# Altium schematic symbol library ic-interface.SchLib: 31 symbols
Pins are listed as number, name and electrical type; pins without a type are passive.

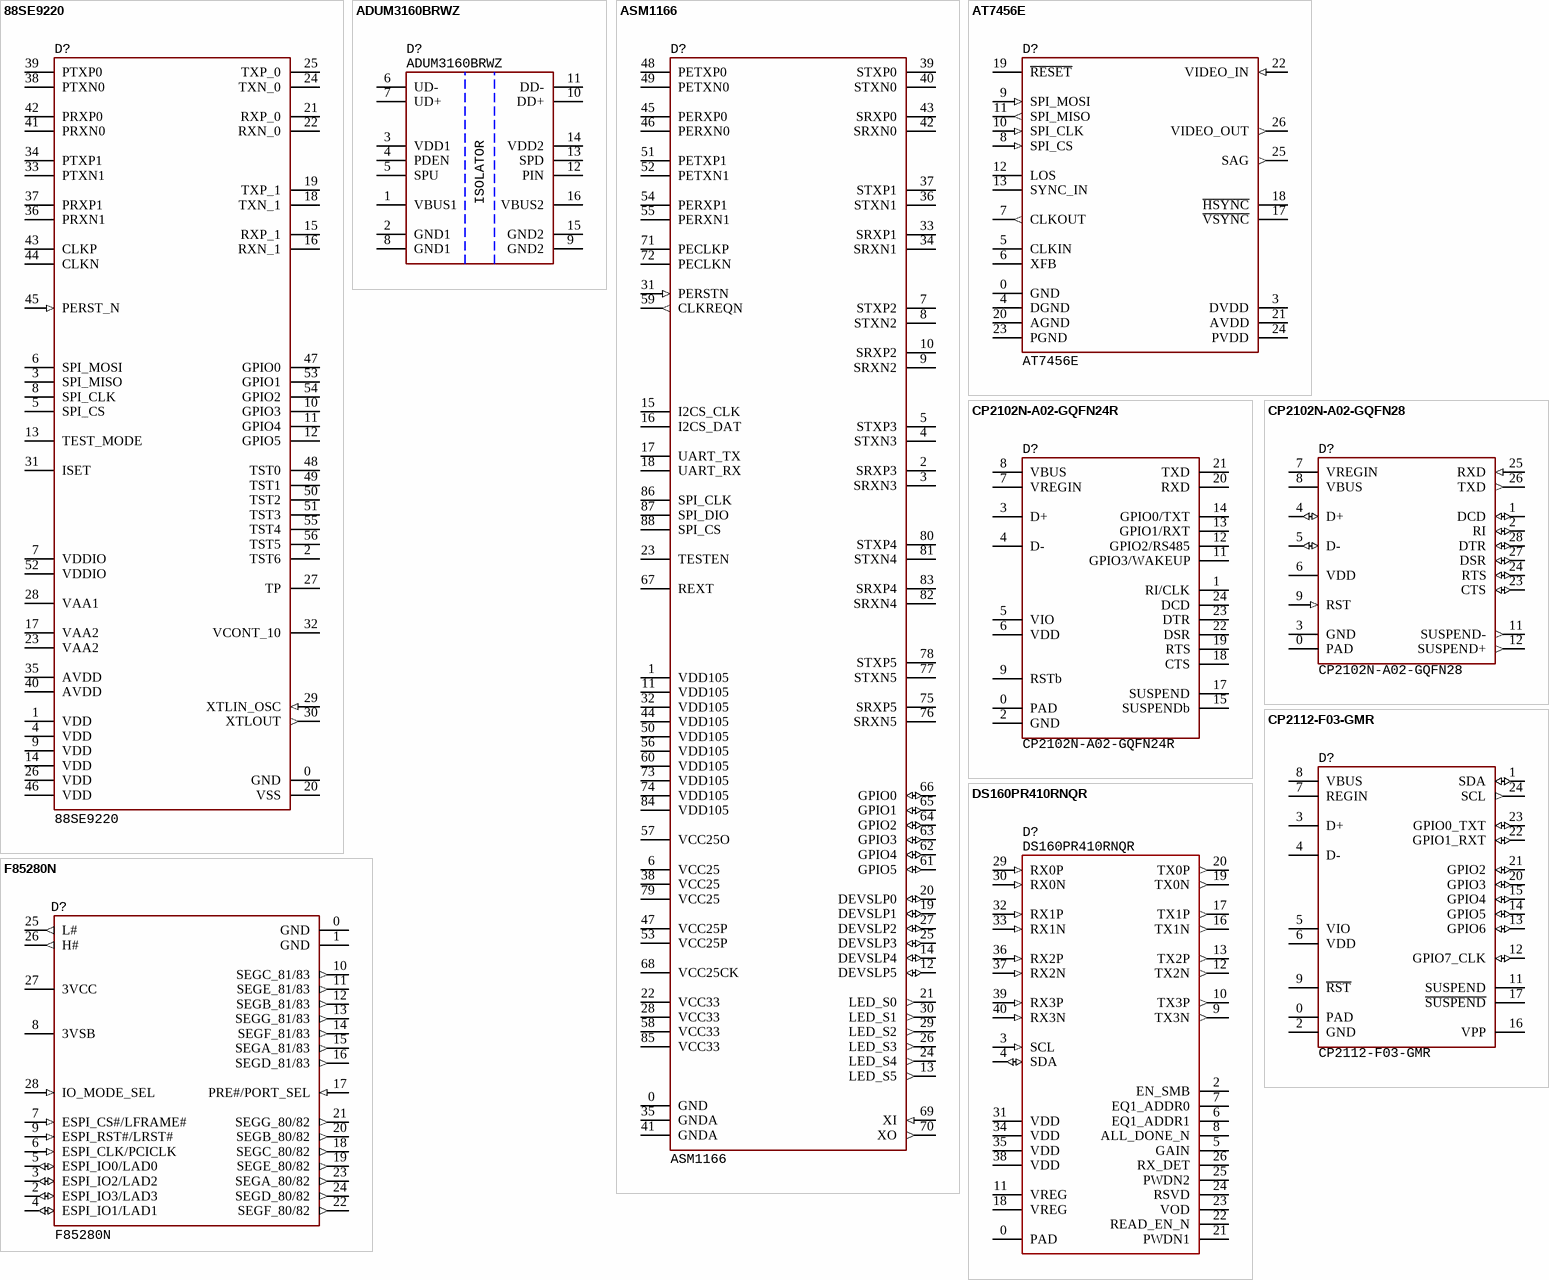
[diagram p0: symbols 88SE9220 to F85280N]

## 88SE9220
designator D?
PCIe Gen 2 to SATA, 2 HDDs, 6 GB/s, QFN-56, -40...+85°C; Manufacturer: Marvell
footprint 56-QFN (7x7, pitch 0.4) (7x7 mm, pitch 0.4 mm, power pad)
pins: 0 GND, 1 VDD, 2 TST6, 3 SPI_MISO, 4 VDD, 5 SPI_CS, 6 SPI_MOSI, 7 VDDIO, 8 SPI_CLK, 9 VDD, 10 GPIO3, 11 GPIO4, 12 GPIO5, 13 TEST_MODE, 14 VDD, 15 RXP_1, 16 RXN_1, 17 VAA2, 18 TXN_1, 19 TXP_1, 20 VSS, 21 RXP_0, 22 RXN_0, 23 VAA2, 24 TXN_0, 25 TXP_0, 26 VDD, 27 TP, 28 VAA1, 29 XTLIN_OSC (in), 30 XTLOUT (out), 31 ISET, 32 VCONT_10, 33 PTXN1, 34 PTXP1, 35 AVDD, 36 PRXN1, 37 PRXP1, 38 PTXN0, 39 PTXP0, 40 AVDD, 41 PRXN0, 42 PRXP0, 43 CLKP, 44 CLKN, 45 PERST_N (in), 46 VDD, 47 GPIO0, 48 TST0, 49 TST1, 50 TST2, 51 TST3, 52 VDDIO, 53 GPIO1, 54 GPIO2, 55 TST4, 56 TST5

## ADUM3160BRWZ
designator D?
USB isolator, 12 Mb/s, supply 3.1...5.5V, 2500 Vrms, SOIC-16, -40...+85°C; Manufacture: Analog Devices
footprint 16-TSSOP (pitch 1.27 mm)
pins: 1 VBUS1, 2 GND1, 3 VDD1, 4 PDEN, 5 SPU, 6 UD-, 7 UD+, 8 GND1, 9 GND2, 10 DD+, 11 DD-, 12 PIN, 13 SPD, 14 VDD2, 15 GND2, 16 VBUS2

## ASM1166
designator D?
PCIe Gen 2 to SATA, 6 HDDs, 6 GB/s, QFN-88, -40...+85°C; Manufacturer: ASMedia
footprint 88-QFN (10x10, pitch 0.4) (10x10 mm, pitch 0.4 mm, power pad)
pins: 0 GND, 1 VDD105, 2 SRXP3, 3 SRXN3, 4 STXN3, 5 STXP3, 6 VCC25, 7 STXP2, 8 STXN2, 9 SRXN2, 10 SRXP2, 11 VDD105, 12 DEVSLP5 (io), 13 LED_S5 (out), 14 DEVSLP4 (io), 15 I2CS_CLK, 16 I2CS_DAT, 17 UART_TX, 18 UART_RX, 19 DEVSLP1 (io), 20 DEVSLP0 (io), 21 LED_S0 (out), 22 VCC33, 23 TESTEN, 24 LED_S4 (out), 25 DEVSLP3 (io), 26 LED_S3 (out), 27 DEVSLP2 (io), 28 VCC33, 29 LED_S2 (out), 30 LED_S1 (out), 31 PERSTN (in), 32 VDD105, 33 SRXP1, 34 SRXN1, 35 GNDA, 36 STXN1, 37 STXP1, 38 VCC25, 39 STXP0, 40 STXN0, 41 GNDA, 42 SRXN0, 43 SRXP0, 44 VDD105, 45 PERXP0, 46 PERXN0, 47 VCC25P, 48 PETXP0, 49 PETXN0, 50 VDD105, 51 PETXP1, 52 PETXN1, 53 VCC25P, 54 PERXP1, 55 PERXN1, 56 VDD105, 57 VCC25O, 58 VCC33, 59 CLKREQN (out), 60 VDD105, 61 GPIO5 (io), 62 GPIO4 (io), 63 GPIO3 (io), 64 GPIO2 (io), 65 GPIO1 (io), 66 GPIO0 (io), 67 REXT, 68 VCC25CK, 69 XI (in), 70 XO (out), 71 PECLKP, 72 PECLKN, 73 VDD105, 74 VDD105, 75 SRXP5, 76 SRXN5, 77 STXN5, 78 STXP5, 79 VCC25, 80 STXP4, 81 STXN4, 82 SRXN4, 83 SRXP4, 84 VDD105, 85 VCC33, 86 SPI_CLK, 87 SPI_DIO, 88 SPI_CS

## AT7456E
designator D?
OSD generator, supply 3.15...5.25V, TSSOP-28, -40...+85°C; Manufacturer: ZHONGKEWEI
footprint 28-TSSOP-PAD (pitch 0.65 mm)
pins: 0 GND, 3 DVDD, 4 DGND, 5 CLKIN, 6 XFB, 7 CLKOUT (out), 8 SPI_CS (in), 9 SPI_MOSI (in), 10 SPI_CLK (in), 11 SPI_MISO (out), 12 LOS, 13 SYNC_IN, 17 ~{VSYNC}, 18 ~{HSYNC}, 19 ~{RESET}, 20 AGND, 21 AVDD, 22 VIDEO_IN (in), 23 PGND, 24 PVDD, 25 SAG (out), 26 VIDEO_OUT (out)

## CP2102N-A02-GQFN24R
designator D?
USB-to-UART, USB2.0, QFN-24, 3...3.6V, -40...+85°C; Manufacturer: Silicon Labs
footprint 24-QFN (4x4, pitch 0.5) (4x4 mm, pitch 0.5 mm, power pad)
pins: 0 PAD, 1 RI/CLK, 2 GND, 3 D+, 4 D-, 5 VIO, 6 VDD, 7 VREGIN, 8 VBUS, 9 RSTb, 11 GPIO3/WAKEUP, 12 GPIO2/RS485, 13 GPIO1/RXT, 14 GPIO0/TXT, 15 SUSPENDb, 17 SUSPEND, 18 CTS, 19 RTS, 20 RXD, 21 TXD, 22 DSR, 23 DTR, 24 DCD

## CP2102N-A02-GQFN28
designator D?  PartNumber: CP2102N-A02-GQFN28
USB-to-UART, USB2.0, QFN-28, 3...3.6V, -40...+85°C; Manufacturer: Silicon Labs
footprint 28-QFN (5x5, pitch 0.5) (5x5 mm, pitch 0.5 mm, power pad)
pins: 0 PAD, 1 DCD (io), 2 RI (io), 3 GND, 4 D+ (io), 5 D- (io), 6 VDD, 7 VREGIN, 8 VBUS, 9 RST (in), 11 SUSPEND- (out), 12 SUSPEND+ (out), 23 CTS (io), 24 RTS (io), 25 RXD (in), 26 TXD (out), 27 DSR (io), 28 DTR (io)

## CP2112-F03-GMR
designator D?
USB-to-I2C, USB2.0, QFN-24, 3...3.6V, -40...+85°C; Manufacturer: Silicon Labs
footprint 24-QFN (4x4, pitch 0.5) (4x4 mm, pitch 0.5 mm, power pad)
pins: 0 PAD, 1 SDA (io), 2 GND, 3 D+, 4 D-, 5 VIO, 6 VDD, 7 REGIN, 8 VBUS, 9 ~{RST}, 11 SUSPEND, 12 GPIO7_CLK (io), 13 GPIO6 (io), 14 GPIO5 (io), 15 GPIO4 (io), 16 VPP, 17 ~{SUSPEND}, 20 GPIO3 (io), 21 GPIO2 (io), 22 GPIO1_RXT (io), 23 GPIO0_TXT (io), 24 SCL (out)

## DS160PR410RNQR
designator D?
Redriver, PCIe Gen 4, 25 GT/s, supply 3...3.6V, 150 mA, -40...+85°C; Manufacture: Texas Instruments
footprint 40-WQFN (6x4, pitch 0.4) (PQFN, 40-Leads, Body 6,00x4,00mm, Pitch 0,40mm, Thermal Pad 4,70x2,70mm, IPC Medium Density)
pins: 0 PAD, 2 EN_SMB, 3 SCL (in), 4 SDA (io), 5 GAIN, 6 EQ1_ADDR1, 7 EQ1_ADDR0, 8 ALL_DONE_N, 9 TX3N (out), 10 TX3P (out), 11 VREG, 12 TX2N (out), 13 TX2P (out), 16 TX1N (out), 17 TX1P (out), 18 VREG, 19 TX0N (out), 20 TX0P (out), 21 PWDN1, 22 READ_EN_N, 23 VOD, 24 RSVD, 25 PWDN2, 26 RX_DET, 29 RX0P (in), 30 RX0N (in), 31 VDD, 32 RX1P (in), 33 RX1N (in), 34 VDD, 35 VDD, 36 RX2P (in), 37 RX2N (in), 38 VDD, 39 RX3P (in), 40 RX3N (in)

## F85280N
designator D?
LPC eSPI interface, 3.3V, QFN-28, -40...+85°C; Manufacturer: Fintek
footprint 28-QFN (4x4, pitch 0.45) (4x4 mm, pitch 0.45 mm, power pad)
pins: 0 GND (power), 1 GND (power), 2 ESPI_IO3/LAD3 (io), 3 ESPI_IO2/LAD2 (io), 4 ESPI_IO1/LAD1 (io), 5 ESPI_IO0/LAD0 (io), 6 ESPI_CLK/PCICLK (in), 7 ESPI_CS#/LFRAME# (in), 8 3VSB (power), 9 ESPI_RST#/LRST# (in), 10 SEGC_81/83 (out), 11 SEGE_81/83 (out), 12 SEGB_81/83 (out), 13 SEGG_81/83 (out), 14 SEGF_81/83 (out), 15 SEGA_81/83 (out), 16 SEGD_81/83 (out), 17 PRE#/PORT_SEL (in), 18 SEGC_80/82 (out), 19 SEGE_80/82 (out), 20 SEGB_80/82 (out), 21 SEGG_80/82 (out), 22 SEGF_80/82 (out), 23 SEGA_80/82 (out), 24 SEGD_80/82 (out), 25 L# (out), 26 H# (out), 27 3VCC (power), 28 IO_MODE_SEL (in)

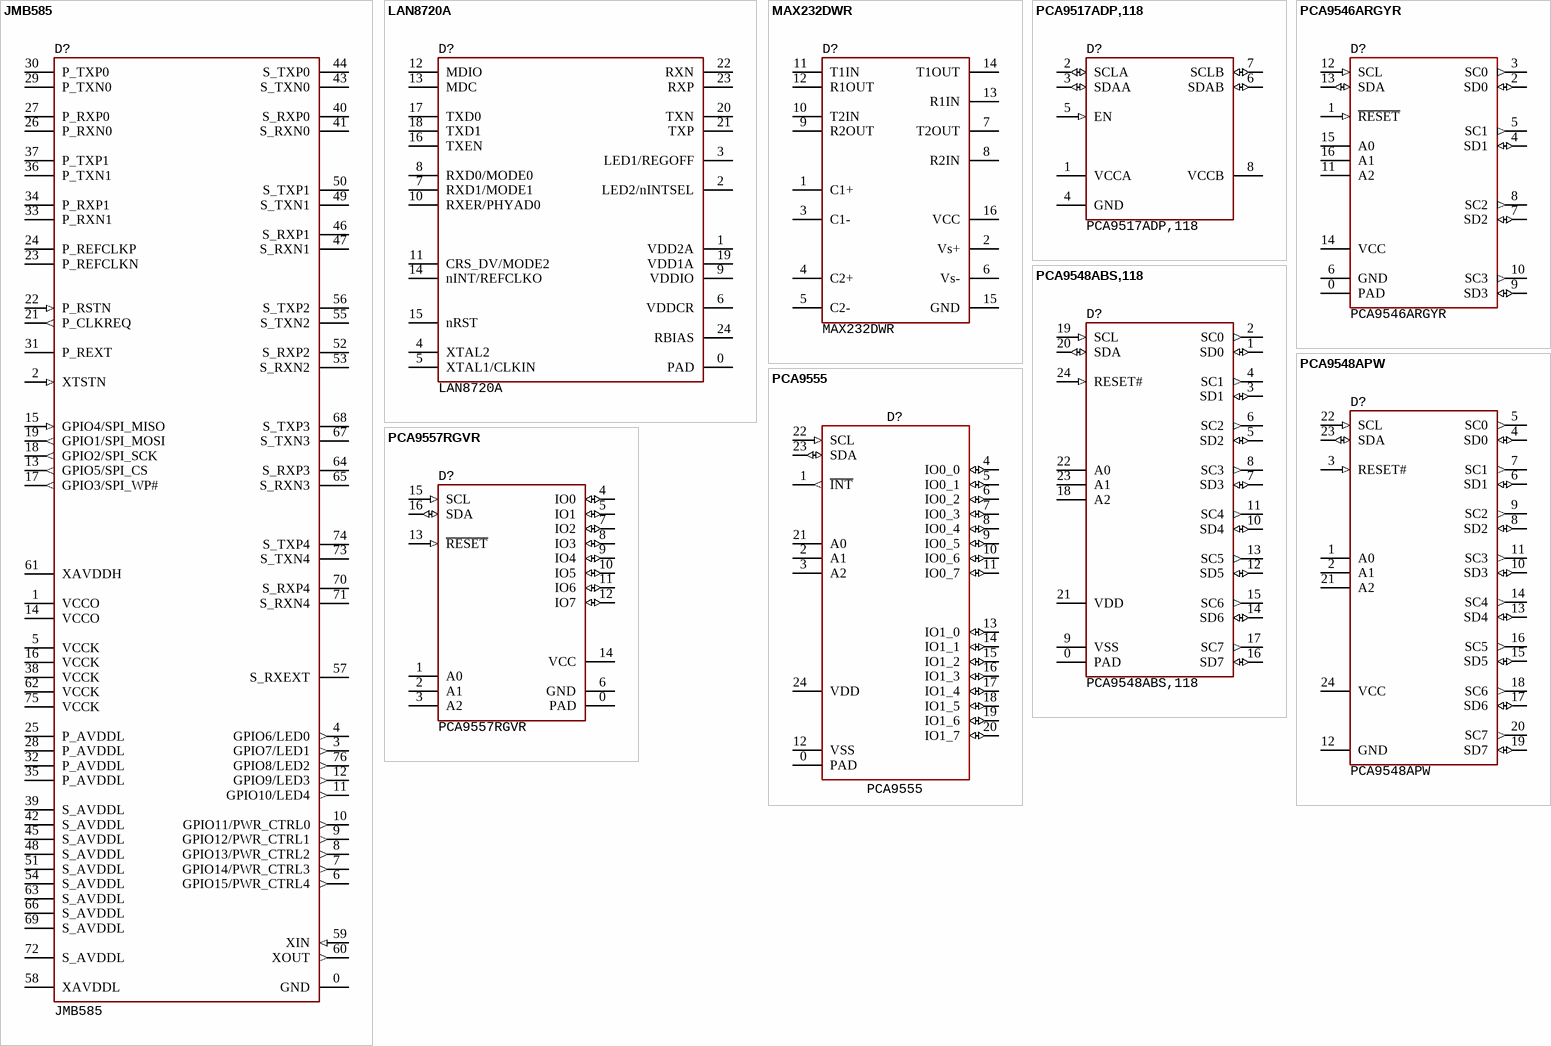
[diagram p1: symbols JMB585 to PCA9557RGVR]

## JMB585
designator D?
PCIe Gen 3 to SATA, 5 HDDs, 6 GB/s, QFN-76, -40...+85°C; Manufacturer: JMicron
footprint 76-QFN (9x9, pitch 0.4) (9x9 mm, pitch 0.4 mm, power pad)
pins: 0 GND, 1 VCCO, 2 XTSTN (in), 3 GPIO7/LED1 (out), 4 GPIO6/LED0 (out), 5 VCCK, 6 GPIO15/PWR_CTRL4 (out), 7 GPIO14/PWR_CTRL3 (out), 8 GPIO13/PWR_CTRL2 (out), 9 GPIO12/PWR_CTRL1 (out), 10 GPIO11/PWR_CTRL0 (out), 11 GPIO10/LED4 (out), 12 GPIO9/LED3 (out), 13 GPIO5/SPI_CS (out), 14 VCCO, 15 GPIO4/SPI_MISO (in), 16 VCCK, 17 GPIO3/SPI_WP# (out), 18 GPIO2/SPI_SCK (out), 19 GPIO1/SPI_MOSI (out), 21 P_CLKREQ (out), 22 P_RSTN (in), 23 P_REFCLKN, 24 P_REFCLKP, 25 P_AVDDL, 26 P_RXN0, 27 P_RXP0, 28 P_AVDDL, 29 P_TXN0, 30 P_TXP0, 31 P_REXT, 32 P_AVDDL, 33 P_RXN1, 34 P_RXP1, 35 P_AVDDL, 36 P_TXN1, 37 P_TXP1, 38 VCCK, 39 S_AVDDL, 40 S_RXP0, 41 S_RXN0, 42 S_AVDDL, 43 S_TXN0, 44 S_TXP0, 45 S_AVDDL, 46 S_RXP1, 47 S_RXN1, 48 S_AVDDL, 49 S_TXN1, 50 S_TXP1, 51 S_AVDDL, 52 S_RXP2, 53 S_RXN2, 54 S_AVDDL, 55 S_TXN2, 56 S_TXP2, 57 S_RXEXT, 58 XAVDDL, 59 XIN (in), 60 XOUT (out), 61 XAVDDH, 62 VCCK, 63 S_AVDDL, 64 S_RXP3, 65 S_RXN3, 66 S_AVDDL, 67 S_TXN3, 68 S_TXP3, 69 S_AVDDL, 70 S_RXP4, 71 S_RXN4, 72 S_AVDDL, 73 S_TXN4, 74 S_TXP4, 75 VCCK, 76 GPIO8/LED2 (out)

## LAN8720A
designator D?  PartNumber: LAN8720A
Ethernet PHY, 10/100 Mbps, RMII, supply 1.6...3.6V, QFN-24, 0...+85°C; Manufacturer: Microchip Technology
footprint 24-QFN (4x4, pitch 0.5) (4x4 mm, pitch 0.5 mm, power pad)
pins: 0 PAD, 1 VDD2A, 2 LED2/nINTSEL, 3 LED1/REGOFF, 4 XTAL2, 5 XTAL1/CLKIN, 6 VDDCR, 7 RXD1/MODE1, 8 RXD0/MODE0, 9 VDDIO, 10 RXER/PHYAD0, 11 CRS_DV/MODE2, 12 MDIO, 13 MDC, 14 nINT/REFCLKO, 15 nRST, 16 TXEN, 17 TXD0, 18 TXD1, 19 VDD1A, 20 TXN, 21 TXP, 22 RXN, 23 RXP, 24 RBIAS

## MAX232DWR
designator D?
RS232-to-UART, USB2.0, TSSOP-16, supply 4.5...5.5V, -65...+150°C; Manufacturer: Texas Instruments
footprint 16-TSSOP (pitch 1.27 mm)
pins: 1 C1+, 2 Vs+, 3 C1-, 4 C2+, 5 C2-, 6 Vs-, 7 T2OUT, 8 R2IN, 9 R2OUT, 10 T2IN, 11 T1IN, 12 R1OUT, 13 R1IN, 14 T1OUT, 15 GND, 16 VCC

## PCA9517ADP,118
designator D?
I2C/SMBus repeater and level shifter, 2.7...5.5V, TSSOP-8, -40...+85°C; Manufacturer: NXP; Manufacturer: NXP Semiconductors
footprint 8-MSOP (pitch 0.65 mm)
pins: 1 VCCA, 2 SCLA (io), 3 SDAA (io), 4 GND, 5 EN (in), 6 SDAB (io), 7 SCLB (io), 8 VCCB

## PCA9546ARGYR
designator D?
I2C/SMBus switch, 4 channels, 2.3...5.5V, VQFN-16, -40...+85°C; Manufacturer: Texas Instruments
footprint 16-QFN (4x4) (4x4 mm, pitch 0.65 mm)
pins: 0 PAD, 1 ~{RESET} (in), 2 SD0 (io), 3 SC0 (out), 4 SD1 (io), 5 SC1 (out), 6 GND, 7 SD2 (io), 8 SC2 (out), 9 SD3 (io), 10 SC3 (out), 11 A2, 12 SCL (in), 13 SDA (io), 14 VCC, 15 A0, 16 A1

## PCA9548ABS,118
designator D?
I2C/SMBus switch, 8 channels, 2.3...5.5V, QFN-24, -40...+85°C; Manufacturer: NXP
footprint 24-QFN (4x4, pitch 0.5) (4x4 mm, pitch 0.5 mm, power pad)
pins: 0 PAD, 1 SD0 (io), 2 SC0 (out), 3 SD1 (io), 4 SC1 (out), 5 SD2 (io), 6 SC2 (out), 7 SD3 (io), 8 SC3 (out), 9 VSS, 10 SD4 (io), 11 SC4 (out), 12 SD5 (io), 13 SC5 (out), 14 SD6 (io), 15 SC6 (out), 16 SD7 (io), 17 SC7 (out), 18 A2, 19 SCL (in), 20 SDA (io), 21 VDD, 22 A0, 23 A1, 24 RESET# (in)

## PCA9548APW
designator D?
I2C/SMBus switch, 8 channels, 2.3...5.5V, TSSOP-24, -40...+85°C; Manufacturer: Texas instruments
footprint 24-TSSOP (4x4 mm, pitch 0.5 mm, power pad)
pins: 1 A0, 2 A1, 3 RESET# (in), 4 SD0 (io), 5 SC0 (out), 6 SD1 (io), 7 SC1 (out), 8 SD2 (io), 9 SC2 (out), 10 SD3 (io), 11 SC3 (out), 12 GND, 13 SD4 (io), 14 SC4 (out), 15 SD5 (io), 16 SC5 (out), 17 SD6 (io), 18 SC6 (out), 19 SD7 (io), 20 SC7 (out), 21 A2, 22 SCL (in), 23 SDA (io), 24 VCC

## PCA9555
designator D?
I2C/SMBus I/O port with interrupt, 2.3...5.5V, VQFN-24, -40...+85°C; Manufacturer: Texas instruments; Manufacturer Part Number: TCA9548ARGER
footprint 24-QFN (4x4, pitch 0.5) (4x4 mm, pitch 0.5 mm, power pad)
pins: 0 PAD, 1 ~{INT} (out), 2 A1, 3 A2, 4 IO0_0 (io), 5 IO0_1 (io), 6 IO0_2 (io), 7 IO0_3 (io), 8 IO0_4 (io), 9 IO0_5 (io), 10 IO0_6 (io), 11 IO0_7 (io), 12 VSS, 13 IO1_0 (io), 14 IO1_1 (io), 15 IO1_2 (io), 16 IO1_3 (io), 17 IO1_4 (io), 18 IO1_5 (io), 19 IO1_6 (io), 20 IO1_7 (io), 21 A0, 22 SCL (in), 23 SDA (io), 24 VDD

## PCA9557RGVR
designator D?
I2C/SMBus IO Extender, 8 channels, 1.65...5.5V, QFN-16, -40...+85°C; Manufacturer: Texas Instruments
footprint 16-QFN (4x4) (4x4 mm, pitch 0.65 mm)
pins: 0 PAD, 1 A0, 2 A1, 3 A2, 4 IO0 (io), 5 IO1 (io), 6 GND, 7 IO2 (io), 8 IO3 (io), 9 IO4 (io), 10 IO5 (io), 11 IO6 (io), 12 IO7 (io), 13 ~{RESET} (in), 14 VCC, 15 SCL (in), 16 SDA (io)

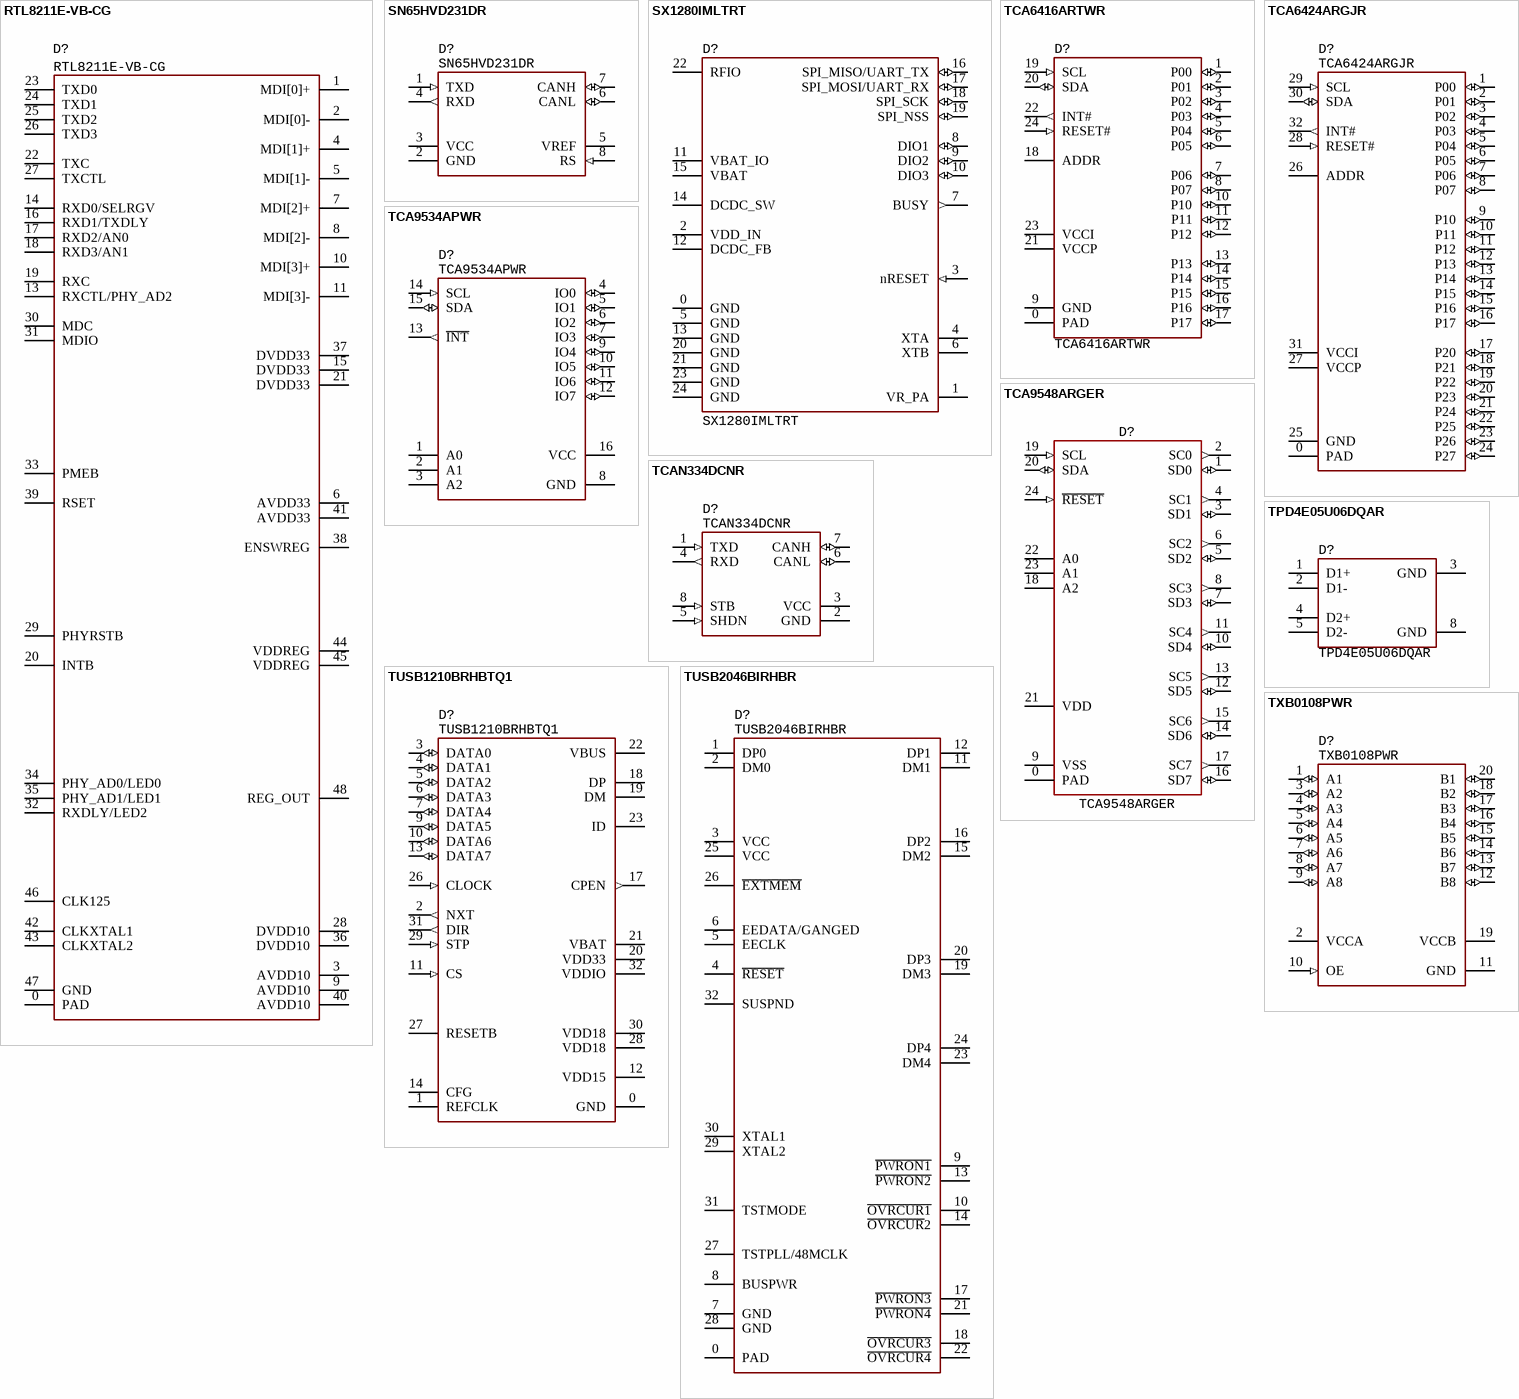
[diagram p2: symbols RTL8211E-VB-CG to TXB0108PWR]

## RTL8211E-VB-CG
designator D?
Ethernet PHY, 10/100/1000 Mbps, RGMII, supply 1.05/3.3V, QFN-48, 0...+70°C; Manufacturer: Realtek
footprint 48-QFN (6x6, pitch 0.4) (6x6 mm, pitch 0.4 mm, power pad)
pins: 0 PAD, 1 MDI[0]+, 2 MDI[0]-, 3 AVDD10, 4 MDI[1]+, 5 MDI[1]-, 6 AVDD33, 7 MDI[2]+, 8 MDI[2]-, 9 AVDD10, 10 MDI[3]+, 11 MDI[3]-, 13 RXCTL/PHY_AD2, 14 RXD0/SELRGV, 15 DVDD33, 16 RXD1/TXDLY, 17 RXD2/AN0, 18 RXD3/AN1, 19 RXC, 20 INTB, 21 DVDD33, 22 TXC, 23 TXD0, 24 TXD1, 25 TXD2, 26 TXD3, 27 TXCTL, 28 DVDD10, 29 PHYRSTB, 30 MDC, 31 MDIO, 32 RXDLY/LED2, 33 PMEB, 34 PHY_AD0/LED0, 35 PHY_AD1/LED1, 36 DVDD10, 37 DVDD33, 38 ENSWREG, 39 RSET, 40 AVDD10, 41 AVDD33, 42 CLKXTAL1, 43 CLKXTAL2, 44 VDDREG, 45 VDDREG, 46 CLK125, 47 GND, 48 REG_OUT

## SN65HVD231DR
designator D?
CAN, 1 Mb/s, supply 3...3.6V, SOIC-8, -40...+85°C; Manufacturer: Texas Instruments
footprint 8-SOIC (pitch 1.27 mm)
pins: 1 TXD (in), 2 GND, 3 VCC, 4 RXD (out), 5 VREF, 6 CANL (io), 7 CANH (io), 8 RS (in)

## SX1280IMLTRT
designator D?
LoRa, 2.4 GHz, 1.3 Mb/s, 12.5 dBm, supply 1.8...3.7V, QFN-24, -40...+85°C; Manufacturer: Semtech
footprint 24-QFN (4x4, pitch 0.5) (4x4 mm, pitch 0.5 mm, power pad)
pins: 0 GND, 1 VR_PA, 2 VDD_IN, 3 nRESET (in), 4 XTA, 5 GND, 6 XTB, 7 BUSY (out), 8 DIO1 (io), 9 DIO2 (io), 10 DIO3 (io), 11 VBAT_IO, 12 DCDC_FB, 13 GND, 14 DCDC_SW, 15 VBAT, 16 SPI_MISO/UART_TX (io), 17 SPI_MOSI/UART_RX (io), 18 SPI_SCK (io), 19 SPI_NSS (io), 20 GND, 21 GND, 22 RFIO, 23 GND, 24 GND

## TCA6416ARTWR
designator D?
I2C/SMBus IO Expander, 16 I/O, 1.65...5.5V, WQFN-24, -40...+85°C; Manufacturer: Texas instruments
footprint 24-QFN (4x4, pitch 0.5) (4x4 mm, pitch 0.5 mm, power pad)
pins: 0 PAD, 1 P00 (io), 2 P01 (io), 3 P02 (io), 4 P03 (io), 5 P04 (io), 6 P05 (io), 7 P06 (io), 8 P07 (io), 9 GND, 10 P10 (io), 11 P11 (io), 12 P12 (io), 13 P13 (io), 14 P14 (io), 15 P15 (io), 16 P16 (io), 17 P17 (io), 18 ADDR, 19 SCL (in), 20 SDA (io), 21 VCCP, 22 INT# (out), 23 VCCI, 24 RESET# (in)

## TCA6424ARGJR
designator D?
I2C/SMBus IO Extender, 24 channels, 25 mA, 1.65...5.5V, QFN-32, -40...+85°C; Manufacturer: Texas Instruments
footprint 32-QFN (5x5, pitch 0.5) (5x5 mm, pitch 0.5 mm, power pad)
pins: 0 PAD, 1 P00 (io), 2 P01 (io), 3 P02 (io), 4 P03 (io), 5 P04 (io), 6 P05 (io), 7 P06 (io), 8 P07 (io), 9 P10 (io), 10 P11 (io), 11 P12 (io), 12 P13 (io), 13 P14 (io), 14 P15 (io), 15 P16 (io), 16 P17 (io), 17 P20 (io), 18 P21 (io), 19 P22 (io), 20 P23 (io), 21 P24 (io), 22 P25 (io), 23 P26 (io), 24 P27 (io), 25 GND, 26 ADDR, 27 VCCP, 28 RESET# (in), 29 SCL (in), 30 SDA (io), 31 VCCI, 32 INT# (out)

## TCA9534APWR
designator D?
I2C/SMBus IO Extender, 8 channels, 25 mA, 1.65...5.5V, TSSOP-16, -40...+85°C; Manufacturer: Texas Instruments
footprint 16-SSOP (pitch 0.635 mm)
pins: 1 A0, 2 A1, 3 A2, 4 IO0 (io), 5 IO1 (io), 6 IO2 (io), 7 IO3 (io), 8 GND, 9 IO4 (io), 10 IO5 (io), 11 IO6 (io), 12 IO7 (io), 13 ~{INT} (out), 14 SCL (in), 15 SDA (io), 16 VCC

## TCA9548ARGER
designator D?
I2C/SMBus switch, 8 channels, 1.65...5.5V, VQFN-24, -40...+85°C; Manufacturer: Texas instruments
footprint 24-QFN (4x4, pitch 0.5) (4x4 mm, pitch 0.5 mm, power pad)
pins: 0 PAD, 1 SD0 (io), 2 SC0 (out), 3 SD1 (io), 4 SC1 (out), 5 SD2 (io), 6 SC2 (out), 7 SD3 (io), 8 SC3 (out), 9 VSS, 10 SD4 (io), 11 SC4 (out), 12 SD5 (io), 13 SC5 (out), 14 SD6 (io), 15 SC6 (out), 16 SD7 (io), 17 SC7 (out), 18 A2, 19 SCL (in), 20 SDA (io), 21 VDD, 22 A0, 23 A1, 24 ~{RESET} (in)

## TCAN334DCNR
designator D?
CAN, 1 Mb/s, supply 3...3.6V, SOT23-8, -40...+85°C; Manufacturer: Texas Instruments
footprint SOT23-8 (pitch 0.95 mm)
pins: 1 TXD (in), 2 GND, 3 VCC, 4 RXD (out), 5 SHDN (in), 6 CANL (io), 7 CANH (io), 8 STB (in)

## TPD4E05U06DQAR
designator D?
Protection ESD, 5.5V, 4 channels, 0.5 pF, 5A peak, uDFN-10, -40...+125°C; Manufacturer: Texas Instruments
footprint 10-DFN (2.5x1) (3x3 mm, pitch 0.5 mm, power pad)
pins: 1 D1+, 2 D1-, 3 GND, 4 D2+, 5 D2-, 8 GND

## TUSB1210BRHBTQ1
designator D?
USB2.0 PHY, 480 Mb/s, supply 2.7...4.8V, QFN-32, -40...+85°C; Manufacturer: Texas Instruments
footprint 32-QFN (5x5, pitch 0.5) (5x5 mm, pitch 0.5 mm, power pad)
pins: 0 GND, 1 REFCLK, 2 NXT (out), 3 DATA0 (io), 4 DATA1 (io), 5 DATA2 (io), 6 DATA3 (io), 7 DATA4 (io), 9 DATA5 (io), 10 DATA6 (io), 11 CS (in), 12 VDD15, 13 DATA7 (io), 14 CFG, 17 CPEN (out), 18 DP, 19 DM, 20 VDD33, 21 VBAT, 22 VBUS, 23 ID, 26 CLOCK (in), 27 RESETB, 28 VDD18, 29 STP (in), 30 VDD18, 31 DIR (out), 32 VDDIO

## TUSB2046BIRHBR
designator D?
USB hub, 4 ports, USB2.0, supply 3...3.6V, QFN-32, -40...+85°C; Manufacturer: Texas Instruments
footprint 32-QFN (5x5, pitch 0.5) (5x5 mm, pitch 0.5 mm, power pad)
pins: 0 PAD, 1 DP0, 2 DM0, 3 VCC, 4 ~{RESET}, 5 EECLK, 6 EEDATA/GANGED, 7 GND, 8 BUSPWR, 9 ~{PWRON1}, 10 ~{OVRCUR1}, 11 DM1, 12 DP1, 13 ~{PWRON2}, 14 ~{OVRCUR}2, 15 DM2, 16 DP2, 17 ~{PWRON3}, 18 ~{OVRCUR3}, 19 DM3, 20 DP3, 21 ~{PWRON4}, 22 ~{OVRCUR4}, 23 DM4, 24 DP4, 25 VCC, 26 ~{EXTMEM}, 27 TSTPLL/48MCLK, 28 GND, 29 XTAL2, 30 XTAL1, 31 TSTMODE, 32 SUSPND

## TXB0108PWR
designator D?
Level translator, 100 Mb/s, 1.2...5V level, TSSOP-20, -40...+85°C; Manufacturer: Texas Instruments
footprint 20-TSSOP (pitch 0.65 mm)
pins: 1 A1 (io), 2 VCCA, 3 A2 (io), 4 A3 (io), 5 A4 (io), 6 A5 (io), 7 A6 (io), 8 A7 (io), 9 A8 (io), 10 OE (in), 11 GND, 12 B8 (io), 13 B7 (io), 14 B6 (io), 15 B5 (io), 16 B4 (io), 17 B3 (io), 18 B2 (io), 19 VCCB, 20 B1 (io)

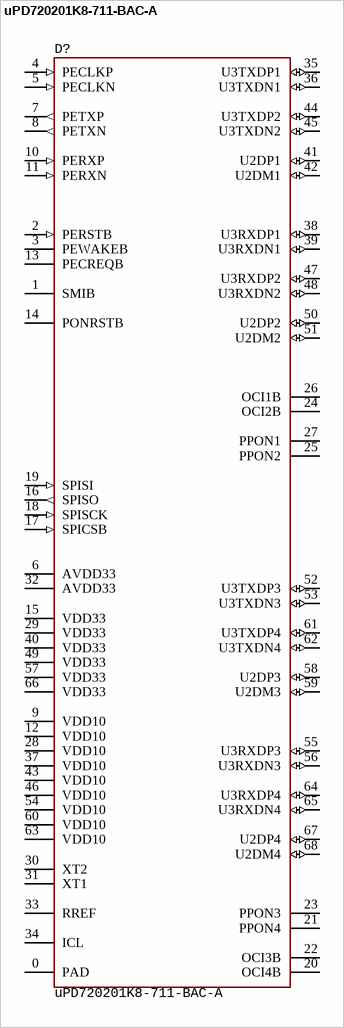
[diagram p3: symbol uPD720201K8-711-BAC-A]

## uPD720201K8-711-BAC-A
designator D?
PCIe to USB3.0, 5 GT/s, 1.05...3.3V, QFN-68, 0...+85°C; Manufacturer: Renesas
footprint 68-QFN (8x8, pitch 0.5) (9x9 mm, pitch 0.5 mm, power pad)
pins: 0 PAD, 1 SMIB, 2 PERSTB (in), 3 PEWAKEB, 4 PECLKP (in), 5 PECLKN (in), 6 AVDD33, 7 PETXP (out), 8 PETXN (out), 9 VDD10, 10 PERXP (in), 11 PERXN (in), 12 VDD10, 13 PECREQB, 14 PONRSTB, 15 VDD33, 16 SPISO (out), 17 SPICSB (in), 18 SPISCK (in), 19 SPISI (in), 20 OCI4B, 21 PPON4, 22 OCI3B, 23 PPON3, 24 OCI2B, 25 PPON2, 26 OCI1B, 27 PPON1, 28 VDD10, 29 VDD33, 30 XT2, 31 XT1, 32 AVDD33, 33 RREF, 34 ICL, 35 U3TXDP1 (io), 36 U3TXDN1 (io), 37 VDD10, 38 U3RXDP1 (io), 39 U3RXDN1 (io), 40 VDD33, 41 U2DP1 (io), 42 U2DM1 (io), 43 VDD10, 44 U3TXDP2 (io), 45 U3TXDN2 (io), 46 VDD10, 47 U3RXDP2 (io), 48 U3RXDN2 (io), 49 VDD33, 50 U2DP2 (io), 51 U2DM2 (io), 52 U3TXDP3 (io), 53 U3TXDN3 (io), 54 VDD10, 55 U3RXDP3 (io), 56 U3RXDN3 (io), 57 VDD33, 58 U2DP3 (io), 59 U2DM3 (io), 60 VDD10, 61 U3TXDP4 (io), 62 U3TXDN4 (io), 63 VDD10, 64 U3RXDP4 (io), 65 U3RXDN4 (io), 66 VDD33, 67 U2DP4 (io), 68 U2DM4 (io)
